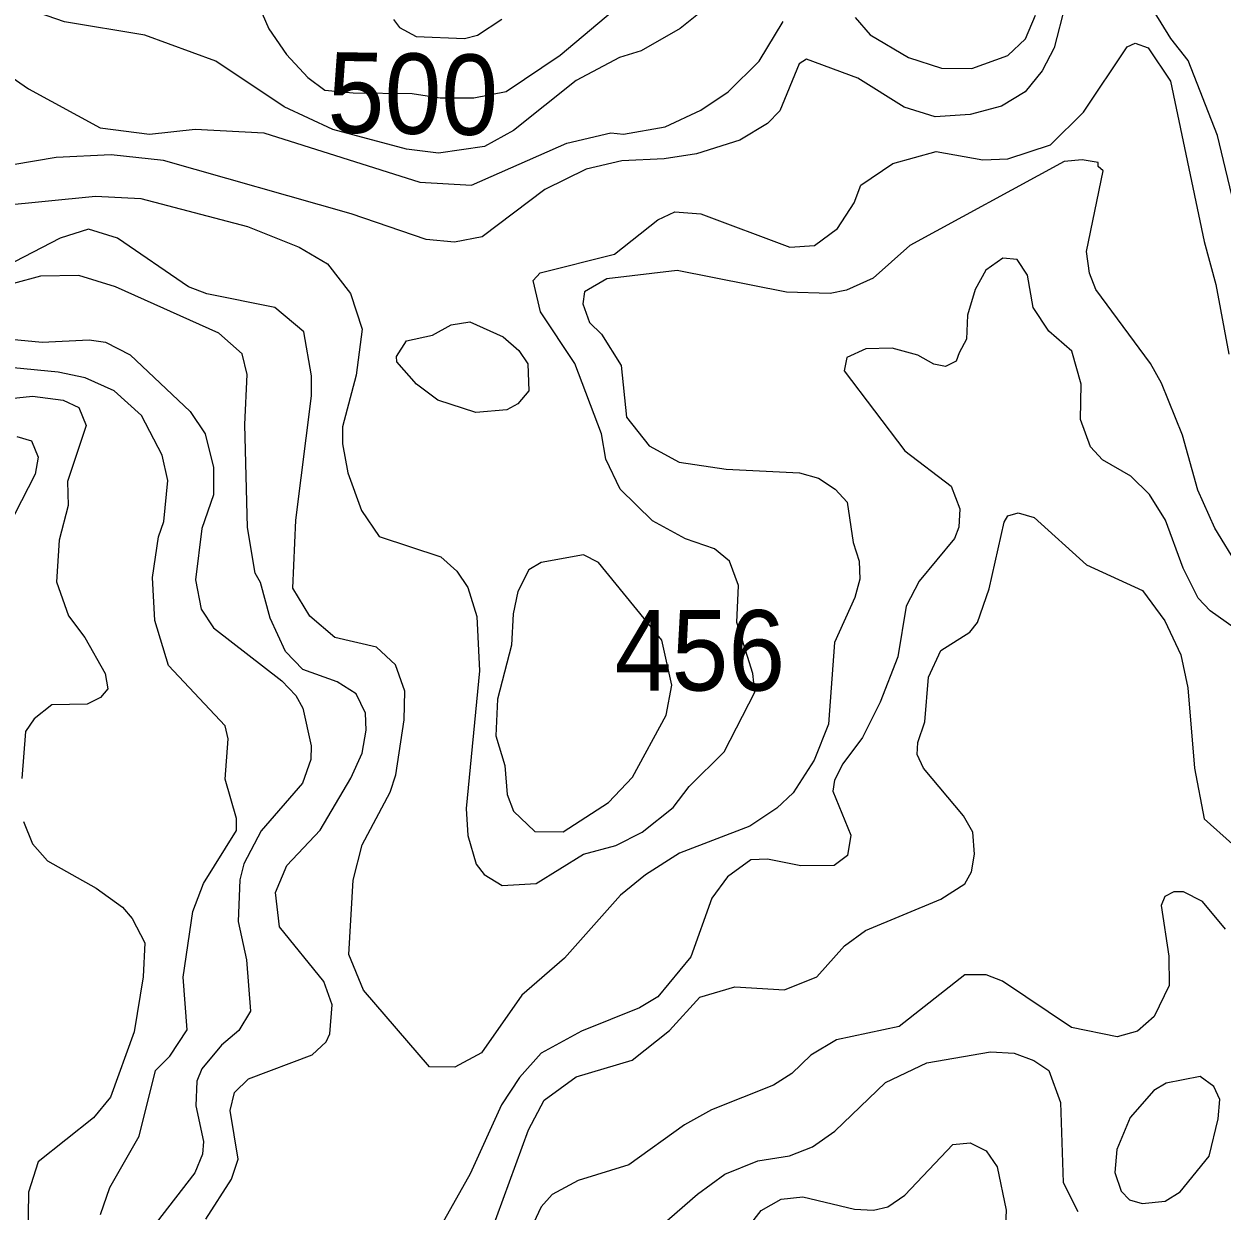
# Model space of a CAD drawing. Extents: x 673.6 to 698.9, y 7012 to 7040.1.
# Drawn here: x 676.578 to 677.77, y 7036.731 to 7037.912 of the extents above; entities that cross this region are included whole.
import ezdxf
from ezdxf.enums import TextEntityAlignment as Align

# ---------------------------------------------------------------- set-up
doc = ezdxf.new("R2010")
doc.units = 0
doc.header["$LTSCALE"] = 0.032
doc.layers.add('1', color=7, linetype='Continuous', lineweight=25)
doc.layers.add('2', color=7, linetype='Continuous', lineweight=13)
doc.layers.add('21', color=7, linetype='Continuous')
doc.layers.add('61', color=7, linetype='Continuous')

msp = doc.modelspace()

# ---------------------------------------------------------------- linework, layer by layer
at = {"layer": '1'}
for points in [[(676.8095, 7037.9354), (676.8216, 7037.907), (676.8392, 7037.8816), (676.8605, 7037.8587), (676.8776, 7037.8462), (676.9056, 7037.8433), (676.9644, 7037.8427), (676.9921, 7037.8383), (677.0256, 7037.8386), (677.0579, 7037.8447), (677.1116, 7037.8808), (677.1948, 7037.9513)], [(677.7867, 7037.3716), (677.7634, 7037.4103), (677.7462, 7037.4481), (677.7312, 7037.5027), (677.7102, 7037.5546), (677.6992, 7037.5742), (677.6448, 7037.6477), (677.6385, 7037.6641), (677.6354, 7037.6856), (677.6523, 7037.7659), (677.6472, 7037.77), (677.6472, 7037.7742), (677.6311, 7037.7767), (677.6132, 7037.775), (677.4597, 7037.6915), (677.4231, 7037.6589), (677.3967, 7037.647), (677.3803, 7037.6437), (677.3369, 7037.6452), (677.2281, 7037.6666), (677.1582, 7037.6584), (677.1359, 7037.6454), (677.1341, 7037.6335), (677.1409, 7037.615), (677.1527, 7037.6033), (677.1724, 7037.5719), (677.1776, 7037.5205), (677.2004, 7037.492), (677.23, 7037.4758), (677.2769, 7037.4688), (677.35, 7037.4653), (677.3689, 7037.4599), (677.3854, 7037.4489), (677.3974, 7037.436), (677.4034, 7037.3958), (677.4092, 7037.3774), (677.41, 7037.3593), (677.4051, 7037.3413), (677.3846, 7037.2964), (677.3788, 7037.2151), (677.3644, 7037.1793), (677.3437, 7037.1467), (677.3275, 7037.1316), (677.3004, 7037.1135), (677.2305, 7037.0866), (677.1965, 7037.0653), (677.1719, 7037.0448), (677.1161, 7036.9824), (677.0734, 7036.9454), (677.0333, 7036.8882)], [(676.9058, 7037.06), (676.9147, 7037.0951), (676.9424, 7037.1474), (676.948, 7037.1646), (676.9564, 7037.2193), (676.9572, 7037.248), (676.9479, 7037.2741), (676.9289, 7037.2919), (676.8874, 7037.3013), (676.8626, 7037.3225), (676.8456, 7037.3506), (676.8487, 7037.4182), (676.8643, 7037.5419), (676.8643, 7037.5618), (676.8565, 7037.6055), (676.8278, 7037.6297), (676.7599, 7037.6433), (676.7418, 7037.6504), (676.6712, 7037.6987), (676.6423, 7037.7076), (676.6139, 7037.6987), (676.5685, 7037.6751)], [(676.571, 7037.5014), (676.5856, 7037.4971), (676.5923, 7037.4809), (676.5892, 7037.464), (676.5687, 7037.4238)], [(677.0333, 7036.8882), (677.0069, 7036.8738), (676.9815, 7036.8741), (676.916, 7036.9505), (676.9015, 7036.9859), (676.9058, 7037.06)], [(677.2991, 7036.715), (677.3119, 7036.731), (677.3318, 7036.7425), (677.3532, 7036.7447), (677.4047, 7036.7323), (677.4234, 7036.7315), (677.4377, 7036.7347), (677.4547, 7036.7465), (677.5024, 7036.7968), (677.5197, 7036.7986), (677.5357, 7036.7906), (677.5465, 7036.7746), (677.5555, 7036.7315), (677.5539, 7036.6934)]]:
    msp.add_lwpolyline(points, dxfattribs=at)
at = {"layer": '2'}
for points in [[(677.2516, 7038.0566), (677.2515, 7038.0401), (677.281, 7037.9802), (677.2774, 7037.9534), (677.266, 7037.9354), (677.2312, 7037.9074), (677.1923, 7037.8853), (677.1706, 7037.8785), (677.1276, 7037.8556), (677.0652, 7037.8058), (677.0364, 7037.7901), (676.9907, 7037.7834), (676.9589, 7037.7874), (676.8855, 7037.8069), (676.8371, 7037.8295), (676.7689, 7037.8749), (676.6984, 7037.9008), (676.6184, 7037.914), (676.5742, 7037.9293)], [(677.6793, 7037.9628), (677.6585, 7037.981), (677.6399, 7037.9821), (677.6314, 7037.9731), (677.6142, 7037.9308), (677.6035, 7037.8881)], [(677.8167, 7037.5897), (677.7659, 7037.8009), (677.7369, 7037.8756), (677.7195, 7037.8974), (677.6793, 7037.9628)], [(676.5129, 7037.8956), (676.5825, 7037.8474), (676.6539, 7037.8087), (676.7028, 7037.8023), (676.7485, 7037.8071), (676.8167, 7037.8037), (676.9721, 7037.7545), (677.0233, 7037.7514), (677.1183, 7037.7932), (677.162, 7037.8037), (677.1746, 7037.8023), (677.2162, 7037.8095), (677.2517, 7037.8262), (677.2788, 7037.8445), (677.3099, 7037.8748), (677.3336, 7037.9143)], [(676.9458, 7037.9165), (676.9518, 7037.9083), (676.9685, 7037.8994), (677.0164, 7037.8976), (677.0293, 7037.9009), (677.0536, 7037.9168)], [(677.4053, 7037.9183), (677.4203, 7037.901), (677.4585, 7037.8786), (677.4911, 7037.868), (677.5215, 7037.8677), (677.5574, 7037.8805), (677.5749, 7037.8971), (677.5849, 7037.9207)], [(677.6035, 7037.8881), (677.5914, 7037.8652), (677.5745, 7037.8443), (677.551, 7037.8303), (677.5197, 7037.822), (677.4849, 7037.8196), (677.454, 7037.8292), (677.4081, 7037.8579), (677.357, 7037.877), (677.3497, 7037.8723), (677.3303, 7037.8255), (677.3179, 7037.813), (677.2906, 7037.7963), (677.2473, 7037.7827), (677.2153, 7037.7776), (677.1729, 7037.7759), (677.1377, 7037.7676), (677.0964, 7037.7471), (677.0342, 7037.7), (677.0064, 7037.6949), (676.9784, 7037.6975), (676.9038, 7037.7231), (676.717, 7037.776), (676.6648, 7037.7817), (676.6102, 7037.7792), (676.5668, 7037.7719)], [(676.9928, 7037.3817), (677.009, 7037.3675), (677.0197, 7037.3512), (677.0288, 7037.3224), (677.0313, 7037.2683), (677.0181, 7037.1311), (677.0198, 7037.1043), (677.028, 7037.0758), (677.0359, 7037.0655), (677.0539, 7037.0546), (677.0878, 7037.0564), (677.1348, 7037.0856), (677.167, 7037.0945), (677.1933, 7037.1076), (677.2241, 7037.1322), (677.24, 7037.1531), (677.2748, 7037.1877), (677.3056, 7037.247), (677.3036, 7037.2656), (677.2876, 7037.3163), (677.2891, 7037.353), (677.2802, 7037.3774), (677.2654, 7037.3897), (677.2363, 7037.3997), (677.2036, 7037.4175), (677.1714, 7037.449), (677.1573, 7037.4787), (677.1527, 7037.5042), (677.1264, 7037.5739), (677.0921, 7037.6256), (677.0849, 7037.6567), (677.0918, 7037.6644), (677.1657, 7037.683), (677.209, 7037.7169), (677.2258, 7037.725), (677.2516, 7037.723), (677.3402, 7037.6897), (677.3648, 7037.6914), (677.3876, 7037.7083), (677.4043, 7037.7341), (677.4111, 7037.7515), (677.4428, 7037.773), (677.4858, 7037.7849), (677.5325, 7037.7768), (677.5574, 7037.7776), (677.5998, 7037.7916), (677.6325, 7037.8242), (677.6759, 7037.8893), (677.6841, 7037.8927), (677.697, 7037.8883), (677.7192, 7037.855), (677.7526, 7037.6953), (677.7643, 7037.6528), (677.7772, 7037.5835)], [(676.5519, 7037.7308), (676.6492, 7037.7406), (676.6943, 7037.7381), (676.8005, 7037.7104), (676.8518, 7037.6898), (676.8801, 7037.6732), (676.9029, 7037.6438), (676.9145, 7037.6082), (676.9086, 7037.5624), (676.8949, 7037.5109)], [(677.7825, 7037.3109), (677.7585, 7037.3279), (677.7466, 7037.3406), (677.7318, 7037.3704), (677.7142, 7037.4182), (677.6984, 7037.4436), (677.6798, 7037.4618), (677.6516, 7037.4783), (677.6396, 7037.4912), (677.6296, 7037.5184), (677.6302, 7037.5535), (677.621, 7037.5864), (677.598, 7037.6062), (677.5823, 7037.6299), (677.5768, 7037.6619), (677.5667, 7037.6774), (677.5523, 7037.6788), (677.5355, 7037.6668), (677.5246, 7037.6477), (677.517, 7037.6223), (677.5162, 7037.5984), (677.5088, 7037.5848), (677.5057, 7037.5764), (677.4952, 7037.5712), (677.4837, 7037.5733), (677.4676, 7037.5822), (677.4421, 7037.5894), (677.4159, 7037.5885), (677.3969, 7037.58), (677.3945, 7037.5667), (677.4546, 7037.4872), (677.501, 7037.4521), (677.5096, 7037.4295), (677.5086, 7037.4113), (677.5043, 7037.3998), (677.4689, 7037.3574), (677.4559, 7037.3327), (677.4478, 7037.2822), (677.4303, 7037.2371), (677.4127, 7037.2019), (677.393, 7037.1758), (677.3848, 7037.1595), (677.3831, 7037.1484), (677.401, 7037.1046), (677.3976, 7037.0844), (677.3843, 7037.0746), (677.3511, 7037.074), (677.3179, 7037.0807), (677.3014, 7037.08), (677.2783, 7037.0632), (677.2628, 7037.0418), (677.2419, 7036.9836), (677.209, 7036.9437), (677.1906, 7036.9329)], [(676.759, 7036.7226), (676.7845, 7036.7624), (676.7911, 7036.7821), (676.7831, 7036.8306), (676.7874, 7036.8484), (676.8016, 7036.8623), (676.8649, 7036.8859), (676.8788, 7036.8989), (676.8825, 7036.9069), (676.8848, 7036.9357), (676.8766, 7036.9591), (676.8325, 7037.0135), (676.8283, 7037.0476), (676.8396, 7037.0746), (676.8728, 7037.1097), (676.9035, 7037.1615), (676.9146, 7037.1862), (676.9186, 7037.209), (676.9178, 7037.2262), (676.9085, 7037.2454), (676.8898, 7037.2573), (676.8556, 7037.2696), (676.8384, 7037.2876), (676.8231, 7037.3205), (676.8134, 7037.356), (676.8081, 7037.3653), (676.8004, 7037.4108), (676.7979, 7037.5135), (676.8003, 7037.5631), (676.7951, 7037.5837), (676.772, 7037.6043), (676.669, 7037.6505), (676.6325, 7037.6617), (676.5944, 7037.6608), (676.5677, 7037.6538)], [(676.5648, 7037.5984), (676.5962, 7037.5952), (676.643, 7037.5975), (676.6592, 7037.5953), (676.6838, 7037.5826), (676.7434, 7037.5264), (676.7583, 7037.5039), (676.7666, 7037.4707), (676.7666, 7037.4432), (676.7551, 7037.4099), (676.7486, 7037.3587), (676.7544, 7037.3295), (676.7666, 7037.311), (676.8348, 7037.2582), (676.8485, 7037.2437), (676.8555, 7037.2309), (676.8637, 7037.1937), (676.8636, 7037.1801), (676.8552, 7037.1565), (676.8142, 7037.1089), (676.7969, 7037.076), (676.793, 7037.0602), (676.7913, 7037.0186), (676.7996, 7036.9806), (676.8036, 7036.9294), (676.7917, 7036.9104), (676.7746, 7036.8956), (676.755, 7036.8721), (676.7502, 7036.8597), (676.7489, 7036.8354)], [(676.6543, 7036.7273), (676.6636, 7036.7541), (676.6925, 7036.8051), (676.7088, 7036.8705), (676.7231, 7036.8847), (676.7403, 7036.911), (676.7363, 7036.9632), (676.746, 7037.0286), (676.7566, 7037.0565), (676.7896, 7037.1094), (676.7895, 7037.1214), (676.7782, 7037.1604), (676.7813, 7037.2006), (676.7781, 7037.2135), (676.7217, 7037.2736), (676.7084, 7037.3184), (676.7058, 7037.3612), (676.7119, 7037.4016), (676.7173, 7037.4169), (676.7212, 7037.4577), (676.7155, 7037.4829), (676.6949, 7037.5223), (676.6678, 7037.5468), (676.6388, 7037.5597), (676.6121, 7037.5655), (676.5332, 7037.5729)], [(676.5424, 7037.5369), (676.5865, 7037.5416), (676.617, 7037.5376), (676.6325, 7037.5301), (676.6399, 7037.5122), (676.6212, 7037.4567), (676.6219, 7037.4329), (676.6129, 7037.3984), (676.6105, 7037.3568), (676.6223, 7037.3228), (676.6386, 7037.3014), (676.6589, 7037.2657), (676.6614, 7037.2504), (676.6542, 7037.2416), (676.641, 7037.2351), (676.6056, 7037.2343), (676.5883, 7037.2205), (676.5796, 7037.2079), (676.5759, 7037.1609)], [(676.8949, 7037.5109), (676.8949, 7037.4942), (676.9005, 7037.4654), (676.9138, 7037.4279), (676.9314, 7037.402), (676.9928, 7037.3817)], [(677.1276, 7036.8643), (677.1835, 7036.8809), (677.2205, 7036.9101), (677.2508, 7036.9434), (677.2854, 7036.9536), (677.3349, 7036.9509), (677.367, 7036.9637), (677.3947, 7036.9946), (677.4155, 7037.0098), (677.4907, 7037.0409), (677.5143, 7037.0562), (677.521, 7037.0682), (677.5241, 7037.0858), (677.5225, 7037.1078), (677.5131, 7037.1239), (677.4732, 7037.1714), (677.4669, 7037.1848), (677.4676, 7037.197), (677.4748, 7037.2176), (677.4782, 7037.2619), (677.4906, 7037.2885), (677.5193, 7037.3068), (677.5271, 7037.3164), (677.5387, 7037.3499), (677.5536, 7037.4161), (677.5573, 7037.4224), (677.5674, 7037.4256), (677.5836, 7037.4207), (677.6356, 7037.3736), (677.6912, 7037.3483), (677.7134, 7037.3179), (677.7296, 7037.284), (677.7363, 7037.2512), (677.7429, 7037.1712), (677.7527, 7037.1209), (677.781, 7037.0957)], [(676.5777, 7037.1181), (676.5866, 7037.096), (676.6013, 7037.0791), (676.6499, 7037.0519), (676.6762, 7037.033)], [(677.7739, 7037.0112), (677.751, 7037.0388), (677.732, 7037.0484), (677.7226, 7037.0484), (677.7134, 7037.0436), (677.71, 7037.0347), (677.7174, 7036.9843), (677.7178, 7036.9551), (677.7028, 7036.9241), (677.6864, 7036.9096), (677.6661, 7036.9041), (677.6207, 7036.9132), (677.5519, 7036.9592), (677.5358, 7036.9656), (677.5145, 7036.9658), (677.449, 7036.9141), (677.3867, 7036.901), (677.3613, 7036.8857), (677.3424, 7036.8675), (677.3239, 7036.8558), (677.2624, 7036.8314), (677.2353, 7036.8163), (677.1799, 7036.7767), (677.1295, 7036.7609), (677.1038, 7036.7472), (677.0929, 7036.7349), (677.0676, 7036.6812)], [(676.6762, 7037.033), (676.6858, 7037.0218), (676.6984, 7036.9974), (676.6968, 7036.9636), (676.6877, 7036.909), (676.6642, 7036.8439)], [(677.1906, 7036.9329), (677.1328, 7036.9097), (677.0928, 7036.8876), (677.0711, 7036.8635), (677.0533, 7036.8363), (677.0221, 7036.7677)], [(677.1725, 7036.6813), (677.2484, 7036.7475), (677.2755, 7036.7672), (677.3083, 7036.7806), (677.3399, 7036.7857), (677.3629, 7036.7946), (677.3852, 7036.81), (677.4354, 7036.8584), (677.4767, 7036.8782), (677.54, 7036.8892), (677.5637, 7036.8876), (677.5832, 7036.8803), (677.5979, 7036.8704), (677.6096, 7036.8387), (677.6124, 7036.7591), (677.6269, 7036.7301)], [(676.9781, 7036.5945), (677.0062, 7036.6327), (677.0361, 7036.6905), (677.0803, 7036.8113), (677.0956, 7036.841), (677.1276, 7036.8643)], [(676.6642, 7036.8439), (676.6472, 7036.8233), (676.592, 7036.7795), (676.5826, 7036.7495), (676.5818, 7036.7039)], [(676.7489, 7036.8354), (676.7568, 7036.7997), (676.7558, 7036.7871), (676.7482, 7036.7687), (676.7095, 7036.7189), (676.6809, 7036.6737)], [(677.0221, 7036.7677), (676.9936, 7036.717)]]:
    msp.add_lwpolyline(points, dxfattribs=at)
for points in [[(676.9899, 7037.5377), (676.9688, 7037.5535), (676.949, 7037.5757), (676.9487, 7037.581), (676.9586, 7037.5967), (676.9846, 7037.6023), (677.0032, 7037.6124), (677.0219, 7037.6156), (677.0548, 7037.6005), (677.0706, 7037.5869), (677.0796, 7037.5737), (677.0805, 7037.547), (677.0695, 7037.534), (677.0585, 7037.5279), (677.0276, 7037.5254)], [(677.1837, 7037.1625), (677.2173, 7037.2242), (677.2228, 7037.2538), (677.2129, 7037.2988), (677.15, 7037.3759), (677.1348, 7037.3837), (677.0928, 7037.376), (677.0804, 7037.3688), (677.0696, 7037.3471), (677.0649, 7037.3248), (677.0632, 7037.2936), (677.0494, 7037.2401), (677.0477, 7037.2034), (677.0565, 7037.174), (677.059, 7037.145), (677.0653, 7037.1287), (677.0865, 7037.1083), (677.1146, 7037.1079), (677.1599, 7037.1372)], [(677.7624, 7036.8546), (677.7488, 7036.8646), (677.715, 7036.858), (677.7026, 7036.8506), (677.679, 7036.8238), (677.6656, 7036.792), (677.6639, 7036.7689), (677.6702, 7036.7504), (677.6784, 7036.7416), (677.6908, 7036.7381), (677.714, 7036.7403), (677.7288, 7036.7496), (677.7575, 7036.7853), (677.7667, 7036.8223), (677.7682, 7036.8415)]]:
    msp.add_lwpolyline(points, close=True, dxfattribs=at)

# ---------------------------------------------------------------- texts
at = {"layer": '21', "width": 0.95}
msp.add_text('456', height=0.08, dxfattribs=at).set_placement((677.166, 7037.2486))
at = {"layer": '61', "width": 0.95}
msp.add_text('500', height=0.08, rotation=359.01, dxfattribs=at).set_placement((676.9645, 7037.8026), align=Align.CENTER)

doc.saveas('drawing.dxf')
